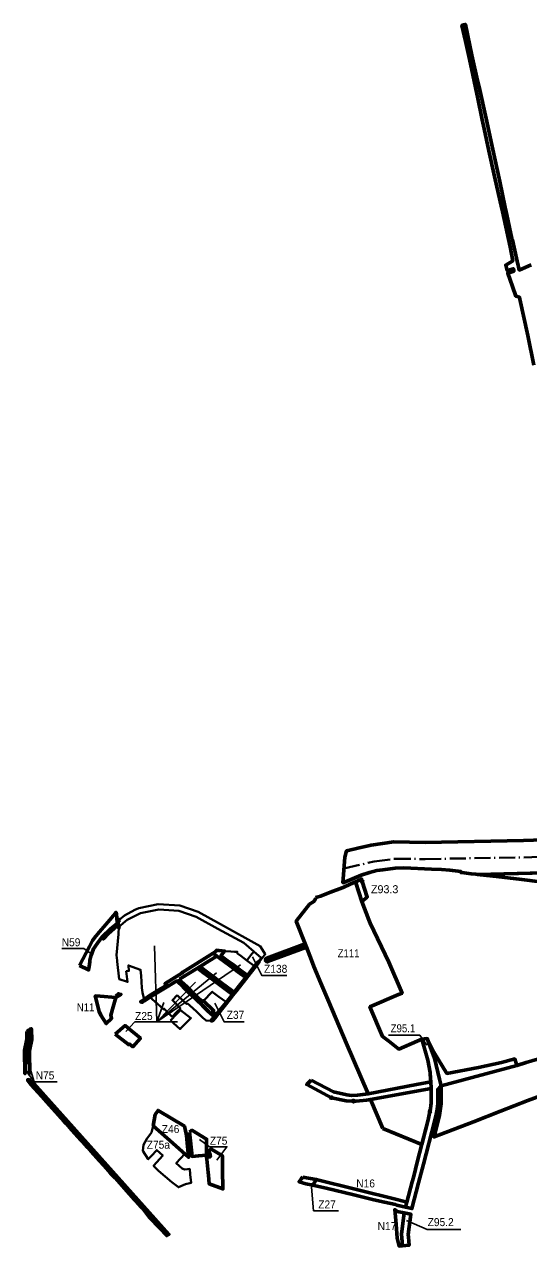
# Model space of a CAD drawing. Extents: x -650277 to -643425, y -1073980 to -1066720.
# Drawn here: x -650277 to -648765, y -1070373 to -1066720 of the extents above; entities that cross this region are included whole.
import ezdxf

# ---------------------------------------------------------------- set-up
doc = ezdxf.new("R2010")
doc.units = 0
doc.header["$LTSCALE"] = 9.6
doc.header["$PDMODE"] = 32
doc.header["$PDSIZE"] = 4.8
doc.linetypes.add('DOT_DASHED', pattern=[7.7, 5, -1.2, 0.3, -1.2])
for name, color, linetype, lineweight in [('1', 7, 'Continuous', 60), ('12', 7, 'Continuous', 60), ('13', 7, 'Continuous', 60), ('15', 7, 'Continuous', 60), ('18', 7, 'Continuous', 60), ('2', 7, 'Continuous', 40), ('24', 7, 'Continuous', 60), ('3', 7, 'Continuous', 60), ('40', 7, 'Continuous', 60), ('42', 7, 'Continuous', 60), ('48', 7, 'Continuous', 60), ('59', 7, 'Continuous', 25), ('60', 7, 'Continuous', 60), ('62', 7, 'DOT_DASHED', 40), ('63', 7, 'Continuous', 25), ('7', 7, 'Continuous', 60), ('9', 7, 'Continuous', 60)]:
    doc.layers.add(name, color=color, linetype=linetype, lineweight=lineweight)

msp = doc.modelspace()

# ---------------------------------------------------------------- linework, layer by layer
at = {"layer": '1'}
for points in [[(-650004.59, -1069747.27), (-649974.86, -1069721.96), (-649966.52, -1069728.87), (-649929.38, -1069759.65), (-649951.56, -1069785.42), (-649963, -1069776.7), (-649965, -1069778.7)], [(-649442.63, -1070176.69), (-649402.29, -1070182.92), (-649404.2, -1070187.43), (-649412.2, -1070200.71), (-649433.3, -1070195.89), (-649453.27, -1070190.02), (-649446.19, -1070180.76)]]:
    msp.add_lwpolyline(points, close=True, dxfattribs=at)
at = {"layer": '12'}
msp.add_lwpolyline([(-649891.21, -1070022.68), (-649832.007, -1070074.751), (-649784.87, -1070116.76), (-649791.31, -1070051.51), (-649797.45, -1070023.77), (-649876.31, -1069975.93), (-649884.59, -1069988.57)], close=True, dxfattribs=at)
at = {"layer": '13'}
msp.add_line((-649202.375, -1070030.469), (-649085.737, -1070078.201), dxfattribs=at)
for points in [[(-649057.868, -1069910.51), (-649239.635, -1069943.094), (-649202.375, -1070030.469)], [(-649085.737, -1070078.201), (-649066.487, -1070004.267), (-649061.139, -1069979.254), (-649061.138, -1069979.243)]]:
    msp.add_lwpolyline(points, dxfattribs=at)
msp.add_arc((-649347.129, -1069931.193), 290, 350.46253, 4.08974, dxfattribs=at)
msp.add_point((-649061.138, -1069979.243), dxfattribs=at)
at = {"layer": '15'}
msp.add_line((-649057.868, -1069910.51), (-649058.82, -1069890.548), dxfattribs=at)
for points in [[(-648749.97, -1067741.49), (-648767.84, -1067652.98), (-648791.68, -1067543.78), (-648792.97, -1067537.86), (-648804.08, -1067534.88), (-648813.94, -1067506.27), (-648827.86, -1067465.86), (-648809.65, -1067459.77), (-648809.97, -1067458.52), (-648811.21, -1067453.52), (-648811.4, -1067452.79), (-648829.54, -1067458.42), (-648834.01, -1067441.81), (-648812.91, -1067429.16), (-648820.39, -1067386.83), (-648844.16, -1067281.37), (-648845.94, -1067272.85), (-648867.82, -1067176.66), (-648884.26, -1067099.63), (-648899.1, -1067033.34), (-648905.06, -1067006.7), (-648917.76, -1066942.65), (-648924.32, -1066909.55), (-648936.7, -1066852.52), (-648944.75, -1066815.41), (-648955.15, -1066770.11), (-648965.39, -1066723.15), (-648959.88, -1066721.59), (-648954.86, -1066720.16), (-648935.19, -1066812.53), (-648918.27, -1066888.41), (-648914.11, -1066907.05), (-648893.02, -1067002.5), (-648872.31, -1067095.5), (-648851.87, -1067191.04), (-648835.29, -1067268.93), (-648833.66, -1067276.77), (-648816.06, -1067361.71), (-648813.81, -1067365.91), (-648799.58, -1067430.4), (-648796.8, -1067443.1), (-648795.88, -1067447.21), (-648794.7, -1067452.46), (-648793.71, -1067456.88), (-648757.97, -1067441.51)], [(-649417.234, -1069885.193), (-649418.94, -1069887.36), (-649430.515, -1069898.514), (-649356.458, -1069937.945)], [(-649246.81, -1069926.27), (-649278.492, -1069930.573), (-649296.851, -1069931.092), (-649310.738, -1069929.342), (-649350.222, -1069920.873), (-649417.234, -1069885.193)], [(-649058.82, -1069890.548), (-649101.89, -1069898.73), (-649246.81, -1069926.27)], [(-649289.95, -1069948.146), (-649282.437, -1069948.342), (-649251.805, -1069945.276), (-649239.635, -1069943.094), (-649057.868, -1069910.51)], [(-649356.458, -1069937.945), (-649312.646, -1069947.342), (-649289.95, -1069948.146)]]:
    msp.add_lwpolyline(points, dxfattribs=at)
for points in [[(-650025.31, -1069446.49), (-649998.512, -1069422.926), (-649999.01, -1069415.628), (-650018.873, -1069431.749), (-650043.521, -1069455.69), (-650045.72, -1069459.1), (-650040.012, -1069461.999)], [(-649547.733, -1069530.185), (-649431.761, -1069486.57), (-649435.578, -1069476.772), (-649550.53, -1069519.68), (-649554.83, -1069525), (-649551.32, -1069528.49), (-649549.69, -1069530.14), (-649548.881, -1069530.963)], [(-648800.85, -1069841.52), (-648806.946, -1069821.79), (-648846.924, -1069832.58), (-648916.03, -1069847.12), (-649010.55, -1069865.09), (-649049.22, -1069801.23), (-649069.4, -1069760.67), (-649048, -1069820), (-649032.928, -1069882.782), (-649028.017, -1069902.109)]]:
    msp.add_lwpolyline(points, close=True, dxfattribs=at)
for p in [(-649356.458, -1069937.945), (-649289.95, -1069948.146)]:
    msp.add_point(p, dxfattribs=at)
at = {"layer": '18'}
for points in [[(-649781.53, -1070041.2), (-649774.45, -1070113.92), (-649754.82, -1070111.89), (-649731.12, -1070109.96), (-649730.96, -1070094.91), (-649730.89, -1070088.96), (-649730.6, -1070061.98), (-649774.73, -1070035.58)], [(-649730.57, -1070115.76), (-649730, -1070122.01), (-649726.22, -1070162.75), (-649725.49, -1070170.64), (-649723.17, -1070195.81), (-649682.04, -1070211.58), (-649683.12, -1070154.14), (-649682.98, -1070132.1), (-649683.57, -1070112.05), (-649717.72, -1070091.61), (-649718.71, -1070093.35), (-649724.36, -1070099.03), (-649719.69, -1070108.94), (-649719.24, -1070114.87)]]:
    msp.add_lwpolyline(points, close=True, dxfattribs=at)
at = {"layer": '2'}
for points in [[(-649639.18, -1069505.96), (-649637.69, -1069506.15), (-649628.36, -1069513.11), (-649609.93, -1069526.87), (-649598.004, -1069510.814), (-649589.257, -1069499.905), (-649619, -1069474), (-649697.525, -1069431.522), (-649762.488, -1069395.854), (-649814.067, -1069377.972), (-649874.391, -1069373.859), (-649929.015, -1069384.784), (-649968.465, -1069405.189), (-649994.293, -1069425.949), (-649994.53, -1069447.61), (-650000.59, -1069511.15), (-649998.81, -1069527.07), (-649998.5, -1069529.88), (-649992.59, -1069582.88), (-649967.81, -1069590.74), (-649971.38, -1069558.79), (-649963.43, -1069557.91), (-649965.26, -1069541.51), (-649928.48, -1069554.57), (-649927.3, -1069572.44)], [(-649927.3, -1069572.44), (-649924.62, -1069608.53), (-649923.17, -1069623.14), (-649918.35, -1069643.45), (-649918.35, -1069643.45), (-649903.292, -1069632.541), (-649877.129, -1069617.006), (-649850.24, -1069600.295), (-649855.34, -1069595.8), (-649805.22, -1069564.32), (-649801.49, -1069561.98), (-649701.57, -1069499.21), (-649701.7, -1069495.89), (-649677.02, -1069498.32), (-649658.01, -1069500.19), (-649647.45, -1069500.23), (-649638.81, -1069500.26), (-649639.18, -1069505.96)], [(-649707.19, -1069577.81), (-649688.76, -1069591.57), (-649670.34, -1069605.34), (-649647.93, -1069622.07), (-649628.8, -1069597.67), (-649613.37, -1069577.98), (-649636.83, -1069560.47), (-649659.26, -1069543.71), (-649681.7, -1069526.96), (-649699.72, -1069513.5), (-649722.6, -1069527.61), (-649749.62, -1069544.29)], [(-649677.02, -1069498.32), (-649687.77, -1069512.44), (-649667.74, -1069527.4), (-649649.31, -1069541.16)], [(-649639.18, -1069505.96), (-649638.81, -1069500.26), (-649647.45, -1069500.23), (-649658.01, -1069500.19), (-649677.02, -1069498.32)], [(-649649.31, -1069541.16), (-649630.88, -1069554.92), (-649608.44, -1069571.69), (-649586.82, -1069544.11), (-649609.93, -1069526.87)], [(-649609.93, -1069526.87), (-649628.36, -1069513.11), (-649637.69, -1069506.15), (-649639.18, -1069505.96)], [(-649597.997, -1069510.805), (-649598.004, -1069510.814), (-649609.93, -1069526.87), (-649586.82, -1069544.11)], [(-649597.935, -1069510.728), (-649597.763, -1069510.865), (-649597.997, -1069510.805)], [(-649571.94, -1069529.24), (-649573.922, -1069527.657), (-649567, -1069519), (-649588, -1069501), (-649589.257, -1069499.905), (-649597.935, -1069510.728)], [(-649586.82, -1069544.11), (-649576.071, -1069530.398), (-649574.1, -1069531.97), (-649571.94, -1069529.24)], [(-649758.29, -1069549.64), (-649785.72, -1069566.56), (-649812.08, -1069582.83)], [(-649671.39, -1069651.93), (-649652.88, -1069628.36), (-649677.124, -1069610.681), (-649696.91, -1069595.47), (-649718.13, -1069579.63), (-649739.75, -1069563.48), (-649758.29, -1069549.64)], [(-649749.62, -1069544.29), (-649748.89, -1069546.2), (-649747.5, -1069547.71), (-649725.62, -1069564.05), (-649707.19, -1069577.81)], [(-649788.91, -1069654.4), (-649781.09, -1069661.69), (-649761.34, -1069680.08), (-649741.61, -1069698.46), (-649732.52, -1069706.92), (-649717.884, -1069707.295), (-649707.985, -1069695.508), (-649723.97, -1069680.13), (-649743.41, -1069661.43), (-649762.85, -1069642.73), (-649782.03, -1069624.28), (-649801.48, -1069605.57), (-649820.02, -1069587.73), (-649846.38, -1069603.8), (-649900.64, -1069636.78)], [(-649812.08, -1069582.83), (-649811.52, -1069584.44), (-649810.49, -1069585.81), (-649793.12, -1069602.51), (-649776.54, -1069618.46), (-649759.97, -1069634.4)], [(-649900.64, -1069636.78), (-649877.82, -1069656.83), (-649859.96, -1069672.53)], [(-649833.94, -1069695.239), (-649819.98, -1069680.92), (-649809.47, -1069670.13), (-649833.38, -1069646.08), (-649818.71, -1069630.64)], [(-649818.71, -1069630.64), (-649802.9, -1069645.96), (-649791, -1069657), (-649788.91, -1069654.4)], [(-649759.97, -1069634.4), (-649743.39, -1069650.35), (-649740.23, -1069647.14)], [(-649740.23, -1069647.14), (-649713.73, -1069620.32), (-649713.73, -1069620.32), (-649693.63, -1069635.33), (-649671.39, -1069651.93)], [(-649859.96, -1069672.53), (-649859.17, -1069673.22), (-649857.49, -1069671.46), (-649833.94, -1069695.239)]]:
    msp.add_lwpolyline(points, dxfattribs=at)
at = {"layer": '2', "lineweight": 60}
for points in [[(-649710.957, -1069505.107), (-649801.49, -1069561.98), (-649805.22, -1069564.32), (-649855.34, -1069595.8), (-649850.24, -1069600.295), (-649877.129, -1069617.006), (-649903.292, -1069632.541), (-649918.35, -1069643.45), (-649928.67, -1069649.89), (-649924.8, -1069652.19), (-649920.45, -1069649.53), (-649917.38, -1069647.56), (-649900.64, -1069636.78), (-649846.38, -1069603.8), (-649820.02, -1069587.73), (-649801.48, -1069605.57), (-649782.03, -1069624.28), (-649762.85, -1069642.73), (-649743.41, -1069661.43), (-649723.97, -1069680.13), (-649707.985, -1069695.508), (-649717.884, -1069707.295), (-649712.64, -1069707.43), (-649705.28, -1069698.11), (-649700.42, -1069691.8), (-649703.15, -1069689.75), (-649712.51, -1069680.75), (-649712.89, -1069679.87), (-649712.54, -1069678.98), (-649709.94, -1069676.28), (-649740.23, -1069647.14), (-649743.39, -1069650.35), (-649759.97, -1069634.4), (-649776.54, -1069618.46), (-649793.12, -1069602.51), (-649810.49, -1069585.81), (-649811.52, -1069584.44), (-649812.08, -1069582.83)], [(-649812.08, -1069582.83), (-649785.72, -1069566.56), (-649758.29, -1069549.64), (-649749.62, -1069544.29), (-649722.6, -1069527.61)], [(-649722.6, -1069527.61), (-649699.72, -1069513.5), (-649710.957, -1069505.107)]]:
    msp.add_lwpolyline(points, dxfattribs=at)
for points in [[(-649677.124, -1069610.681), (-649652.88, -1069628.36), (-649671.39, -1069651.93), (-649703.15, -1069689.75), (-649700.42, -1069691.8), (-649658.13, -1069638.84), (-649651.846, -1069630.82), (-649641.978, -1069618.226), (-649620.45, -1069590.75), (-649574.1, -1069531.97), (-649576.071, -1069530.398), (-649586.82, -1069544.11), (-649608.44, -1069571.69), (-649630.88, -1069554.92), (-649649.31, -1069541.16), (-649667.74, -1069527.4), (-649687.77, -1069512.44), (-649677.02, -1069498.32), (-649701.7, -1069495.89), (-649701.57, -1069499.21), (-649710.957, -1069505.107), (-649699.72, -1069513.5), (-649681.7, -1069526.96), (-649659.26, -1069543.71), (-649636.83, -1069560.47), (-649613.37, -1069577.98), (-649628.8, -1069597.67), (-649647.93, -1069622.07), (-649670.34, -1069605.34), (-649688.76, -1069591.57), (-649707.19, -1069577.81), (-649725.62, -1069564.05), (-649747.5, -1069547.71), (-649748.89, -1069546.2), (-649749.62, -1069544.29), (-649758.29, -1069549.64), (-649739.75, -1069563.48), (-649718.13, -1069579.63), (-649696.91, -1069595.47)], [(-650002.39, -1069633.65), (-650002.65, -1069637.14), (-649987.49, -1069628.6), (-649994.913, -1069626.246)]]:
    msp.add_lwpolyline(points, close=True, dxfattribs=at)
at = {"layer": '2'}
for points in [[(-649713.73, -1069620.32), (-649713.73, -1069620.32), (-649740.23, -1069647.14), (-649709.94, -1069676.28), (-649712.54, -1069678.98), (-649712.89, -1069679.87), (-649712.51, -1069680.75), (-649703.15, -1069689.75), (-649671.39, -1069651.93), (-649693.63, -1069635.33)], [(-649838.99, -1069706.15), (-649820.64, -1069687.33), (-649808.96, -1069675.34), (-649777.94, -1069699.2), (-649792.13, -1069713.65), (-649807.66, -1069729.46), (-649810.41, -1069732.28), (-649819.9, -1069723.61)], [(-649891.21, -1070022.68), (-649895.45, -1070042.15), (-649910.34, -1070061.29), (-649919.55, -1070079.01), (-649922.3, -1070096.9), (-649905.51, -1070122.35), (-649897.03, -1070113.07), (-649880.42, -1070094.87), (-649862.22, -1070111.54), (-649889.87, -1070141.83), (-649874.94, -1070157.19), (-649835.28, -1070191.27), (-649815.33, -1070206.63), (-649794.37, -1070197.2), (-649777.29, -1070193.57), (-649779.75, -1070168.69), (-649781.436, -1070151.591), (-649787.92, -1070152.23), (-649797.33, -1070153.41), (-649804.29, -1070150.68), (-649821.97, -1070134.58), (-649796.4, -1070106.56)]]:
    msp.add_lwpolyline(points, close=True, dxfattribs=at)
at = {"layer": '24'}
for points in [[(-649321.69, -1069307.61), (-649324.3, -1069308.59), (-649359.48, -1069321.82), (-649389.4, -1069333.35), (-649396.52, -1069336.09), (-649403.92, -1069338.26)], [(-649283.702, -1069294.132), (-649284.695, -1069291.033), (-649300.133, -1069297.95), (-649321.69, -1069307.61)], [(-649060.897, -1069861.994), (-649068, -1069825.147), (-649085.41, -1069762.44), (-649085.41, -1069762.44), (-649099.75, -1069768.575), (-649154.76, -1069792.11), (-649184.05, -1069768.45), (-649200.64, -1069756.53), (-649202.99, -1069754.99), (-649241.11, -1069665.9), (-649155.082, -1069629.097), (-649144.57, -1069624.6), (-649184.1, -1069532.2), (-649240.202, -1069414.528), (-649244.08, -1069404.753), (-649265.774, -1069350.068), (-649283.702, -1069294.132)], [(-649403.92, -1069338.26), (-649403.03, -1069340.66), (-649408.81, -1069349.89), (-649422.19, -1069357.99), (-649462.25, -1069408.32), (-649435.578, -1069476.772), (-649431.761, -1069486.57)], [(-649431.761, -1069486.57), (-649416.52, -1069525.68), (-649409.355, -1069544.517), (-649388.438, -1069594.296), (-649379.32, -1069615.71), (-649364.44, -1069650.55), (-649312.03, -1069773.33)], [(-649312.03, -1069773.33), (-649246.81, -1069926.27), (-649101.89, -1069898.73), (-649058.82, -1069890.548)]]:
    msp.add_lwpolyline(points, dxfattribs=at)
msp.add_arc((-649649.71, -1069919.176), 591.583, 2.77379, 5.54687, dxfattribs=at)
at = {"layer": '3', "lineweight": 40}
for points in [[(-649558.601, -1069502.461), (-649570.03, -1069483.83), (-649688.625, -1069418.156), (-649755.971, -1069381.179), (-649810.846, -1069362.154), (-649875.434, -1069357.751), (-649934.363, -1069369.537), (-649945.397, -1069375.277), (-649977.239, -1069391.714), (-649994.329, -1069405.451)], [(-649994.293, -1069425.949), (-649968.465, -1069405.189), (-649929.015, -1069384.784), (-649874.391, -1069373.859)], [(-649874.391, -1069373.859), (-649814.067, -1069377.972), (-649762.488, -1069395.854), (-649697.525, -1069431.522), (-649619, -1069474), (-649589.257, -1069499.905)], [(-649994.329, -1069405.451), (-649994.329, -1069405.451), (-649994.293, -1069425.949), (-649994.293, -1069425.949)], [(-649589.257, -1069499.905), (-649567, -1069519), (-649573.922, -1069527.657), (-649571.94, -1069529.24), (-649561.17, -1069515.83), (-649555.16, -1069508.07), (-649558.601, -1069502.461)]]:
    msp.add_lwpolyline(points, dxfattribs=at)
at = {"layer": '3'}
msp.add_lwpolyline([(-648722.24, -1069817.54), (-648772.48, -1069832.83), (-648800.85, -1069841.52), (-649028.017, -1069902.109), (-649027.135, -1069928.902), (-649027.953, -1069955.702), (-649032.644, -1069990.371), (-649037.411, -1070011.659), (-649048.918, -1070055.852), (-648931.057, -1070010.171), (-648849.532, -1069978.559), (-648767.83, -1069946.87), (-648562.242, -1069870.301)], dxfattribs=at)
for p in [(-649994.329, -1069405.451), (-649994.293, -1069425.949)]:
    msp.add_point(p, dxfattribs=at)
at = {"layer": '40'}
for points in [[(-650002.65, -1069637.14), (-650050.26, -1069633.65), (-650064.77, -1069633.06), (-650052.88, -1069679.49), (-650047.45, -1069690.69), (-650031.64, -1069715.9), (-650015.53, -1069700.21), (-650018.31, -1069690.89), (-650011.15, -1069665.82)], [(-649160.748, -1070243.413), (-649402.29, -1070182.92), (-649404.2, -1070187.43), (-649412.2, -1070200.71), (-649412.2, -1070200.71), (-649408.24, -1070201.62), (-649372.69, -1070209.74), (-649289.83, -1070229.16), (-649229.8, -1070243.94), (-649197.55, -1070251.65), (-649164.91, -1070258.55), (-649160.54, -1070259.96), (-649134.294, -1070266.095), (-649130.712, -1070250.935)]]:
    msp.add_lwpolyline(points, close=True, dxfattribs=at)
at = {"layer": '42'}
msp.add_lwpolyline([(-650112.18, -1069542.11), (-650081.29, -1069484.35), (-650072.5, -1069466.44), (-650063.12, -1069453.54), (-650062.17, -1069454.05), (-650060.29, -1069451.7), (-650057.49, -1069448.18), (-650026.33, -1069411.47), (-650003.73, -1069384.71), (-650002.11, -1069382.8), (-650001.13, -1069388.13), (-649999.95, -1069397.98), (-649999.01, -1069415.628), (-650018.873, -1069431.749), (-650043.521, -1069455.69), (-650045.72, -1069459.1), (-650055.612, -1069471.639), (-650066.897, -1069487.541), (-650069.369, -1069492.132), (-650074.75, -1069506.133), (-650076.365, -1069510.333), (-650079.264, -1069517.874), (-650080.302, -1069525.418), (-650080.802, -1069530.768), (-650082.963, -1069544.736), (-650084.345, -1069554.773)], close=True, dxfattribs=at)
at = {"layer": '48'}
for points in [[(-650270.059, -1069739.232), (-650269.449, -1069762.714), (-650276.214, -1069796.532), (-650275.76, -1069865.474), (-650274.95, -1069865.62), (-650273.87, -1069809.74), (-650273.78, -1069805.2), (-650273.58, -1069794.48), (-650270.15, -1069778.65), (-650267.22, -1069765.1), (-650265.37, -1069741.61), (-650264.91, -1069735.69)], [(-650260.645, -1069868.536), (-650260.748, -1069867.327), (-650261.204, -1069797.969), (-650254.411, -1069764.006), (-650255.21, -1069733.253), (-650255.716, -1069731.162), (-650259.97, -1069732.29), (-650258.74, -1069750.62), (-650257.77, -1069765.2), (-650262.93, -1069794.84), (-650262.77, -1069805.54), (-650262.7, -1069809.89), (-650261.8, -1069868.33)], [(-650257.713, -1069885.547), (-650266.89, -1069883.7), (-650266.68, -1069886.78), (-650262.64, -1069891.57), (-650257.16, -1069898.07), (-650224.71, -1069934.41), (-650209.51, -1069951.43), (-650192.51, -1069970.47), (-650174.3, -1069990.86), (-650157.87, -1070009.26), (-650151.03, -1070016.84), (-650134.26, -1070035.45), (-650106.76, -1070065.96), (-650091.89, -1070082.46), (-650087.18, -1070087.68), (-650076.72, -1070099.29), (-650051.33, -1070127.45), (-650037.78, -1070142.48), (-650018.41, -1070163.97), (-650005.3, -1070178.51), (-649990.95, -1070194.43), (-649977.05, -1070209.85), (-649946.39, -1070243.87), (-649930.46, -1070261.54), (-649924.15, -1070268.55), (-649913.03, -1070282.44), (-649901.59, -1070296.73), (-649871.28, -1070329.01), (-649850.04, -1070351.64), (-649843.513, -1070347.685)]]:
    msp.add_lwpolyline(points, close=True, dxfattribs=at)
at = {"layer": '59'}
for p, q in [((-649880, -1069711), (-649887, -1069483)), ((-649880, -1069711), (-649629, -1069540)), ((-649880, -1069711), (-649701, -1069564)), ((-649880, -1069711), (-649764, -1069592)), ((-649880, -1069711), (-649818, -1069711)), ((-649410, -1070277), (-649417.769, -1070193.978)), ((-649335, -1070277), (-649410, -1070277))]:
    msp.add_line(p, q, dxfattribs=at)
for points in [[(-649490, -1069572), (-649565, -1069572), (-649593, -1069516)], [(-649946, -1069711), (-649880, -1069711), (-649859, -1069653)], [(-649618, -1069711), (-649678, -1069711), (-649706, -1069655)]]:
    msp.add_lwpolyline(points, dxfattribs=at)
at = {"layer": '60'}
for p, q in [((-649058.858, -1069889.759), (-649057.868, -1069910.51)), ((-649057.134, -1069932.873), (-649057.868, -1069910.51)), ((-649146.163, -1070347.543), (-649145.424, -1070357.637))]:
    msp.add_line(p, q, dxfattribs=at)
for points in [[(-648721.315, -1069164.952), (-648781.015, -1069167.44), (-649076.02, -1069172.683), (-649169.781, -1069171.432), (-649237.512, -1069180.731), (-649277.021, -1069189.913), (-649306.455, -1069196.754), (-649311.633, -1069197.958), (-649316.47, -1069216.91), (-649321.32, -1069281.47), (-649322.09, -1069291.73), (-649322.22, -1069293.54), (-649319.72, -1069292.47), (-649267.5, -1069270.41), (-649242.5, -1069263.3), (-649220.18, -1069257.03), (-649202.63, -1069254.4), (-649165.62, -1069249.43), (-649139.63, -1069248.73), (-649056.95, -1069252.55), (-649026.955, -1069254.366), (-649001.3, -1069255.92), (-648968.49, -1069260.36), (-648968.05, -1069263.06), (-648965.8, -1069262.75), (-648937.91, -1069266.51), (-648924.13, -1069268.21), (-648918.889, -1069268.875), (-648673.267, -1069262.895)], [(-649061.138, -1069979.243), (-649061.138, -1069979.243), (-649061.139, -1069979.254), (-649066.487, -1070004.267), (-649098.65, -1070127.795), (-649110.925, -1070177.113), (-649114.174, -1070189.816), (-649130.712, -1070250.935), (-649134.294, -1070266.095), (-649115.159, -1070270.568), (-649095.152, -1070193.731), (-649093.095, -1070186.132), (-649095.152, -1070193.731), (-649080.924, -1070137.409), (-649080.38, -1070136.996), (-649047.131, -1070009.304), (-649042.468, -1069988.477), (-649042.468, -1069988.477), (-649039.966, -1069973.035), (-649037.98, -1069956.626), (-649037.322, -1069942.129), (-649037.137, -1069928.996), (-649037.665, -1069912.977), (-649028.017, -1069902.109), (-649032.928, -1069882.782), (-649048, -1069820), (-649069.4, -1069760.67), (-649085.41, -1069762.44), (-649068, -1069825.147), (-649060.897, -1069861.994)], [(-649138.43, -1070283.6), (-649146.163, -1070347.543), (-649146.163, -1070347.543)], [(-649125.503, -1070355.837), (-649126.069, -1070348.097), (-649118.257, -1070287.455), (-649138.43, -1070283.6)], [(-649145.424, -1070357.637), (-649143.633, -1070382.123), (-649123.693, -1070380.572), (-649125.503, -1070355.837)]]:
    msp.add_lwpolyline(points, dxfattribs=at)
msp.add_lwpolyline([(-648730.66, -1069290.43), (-648656.242, -1069297.116), (-648673.267, -1069262.895), (-648761.189, -1069265.035), (-648918.889, -1069268.875), (-648909.86, -1069270.02), (-648861.49, -1069275.34), (-648785.92, -1069284.2), (-648730.66, -1069290.43)], close=True, dxfattribs=at)
for centre, radius, start, end in [((-649633.43, -1069918.001), 575.266, 2.81398, 5.58706), ((-649347.129, -1069931.193), 290, 350.46253, 4.08974), ((-649347.129, -1069931.193), 290, 359.66809, 4.08974)]:
    msp.add_arc(centre, radius, start, end, dxfattribs=at)
at = {"layer": '62'}
msp.add_lwpolyline([(-649319.032, -1069251.01), (-649228.433, -1069229.954), (-649166.697, -1069221.478), (-649075.909, -1069222.689), (-648779.53, -1069217.422), (-648667.088, -1069212.737)], dxfattribs=at)
at = {"layer": '63'}
for p, q in [((-649973, -1069740), (-649946, -1069711)), ((-650248, -1069890), (-650277, -1069850)), ((-650248, -1069890), (-650261, -1069847))]:
    msp.add_line(p, q, dxfattribs=at)
for points in [[(-650165, -1069491), (-650099, -1069491), (-650081, -1069504)], [(-649185, -1069751), (-649092, -1069751), (-649071, -1069781)], [(-650243, -1069909), (-650248, -1069890), (-650179, -1069890)], [(-649752, -1070063), (-649722, -1070085), (-649670, -1070085), (-649700, -1070125)], [(-648969, -1070333), (-649070, -1070333), (-649132, -1070306)]]:
    msp.add_lwpolyline(points, dxfattribs=at)
at = {"layer": '7'}
msp.add_lwpolyline([(-649138.43, -1070283.6), (-649159.78, -1070279.52), (-649166.86, -1070273.48), (-649162.91, -1070317.47), (-649159.19, -1070358.82), (-649153.64, -1070382.9), (-649148.23, -1070382.48), (-649143.633, -1070382.123), (-649146.163, -1070347.543)], close=True, dxfattribs=at)
at = {"layer": '9'}
msp.add_line((-649283.702, -1069294.132), (-649265.774, -1069350.068), dxfattribs=at)
for points in [[(-649264.156, -1069289.589), (-649266.331, -1069282.804), (-649284.695, -1069291.033), (-649283.702, -1069294.132)], [(-649265.774, -1069350.068), (-649249.069, -1069336.66), (-649264.156, -1069289.589)]]:
    msp.add_lwpolyline(points, dxfattribs=at)
for p in [(-649283.702, -1069294.132), (-649264.156, -1069289.589)]:
    msp.add_point(p, dxfattribs=at)

# ---------------------------------------------------------------- texts
at = {"layer": '59', "width": 0.95}
for s, p in [('Z138', (-649558.387, -1069563.603)), ('Z25', (-649945, -1069705)), ('Z37', (-649670.387, -1069701.603)), ('Z75a', (-649910, -1070091)), ('Z27', (-649396, -1070270))]:
    msp.add_text(s, height=24, dxfattribs=at).set_placement(p)
at = {"layer": '63'}
msp.add_text('Z93.3', height=24, dxfattribs=at).set_placement((-649238, -1069325))
for s, width, p in [('N59', 0.95, (-650165, -1069484)), ('Z111', 0.9, (-649338, -1069517)), ('N11', 0.9, (-650120, -1069679)), ('Z95.1', 0.9, (-649179, -1069742)), ('N75', 0.95, (-650243, -1069883)), ('Z46', 0.95, (-649865, -1070044)), ('Z75', 0.95, (-649721, -1070079)), ('N16', 0.95, (-649282, -1070207)), ('N17', 0.95, (-649218, -1070335)), ('Z95.2', 0.95, (-649068, -1070323))]:
    msp.add_text(s, height=24, dxfattribs=dict(at, width=width)).set_placement(p)

doc.saveas('drawing.dxf')
